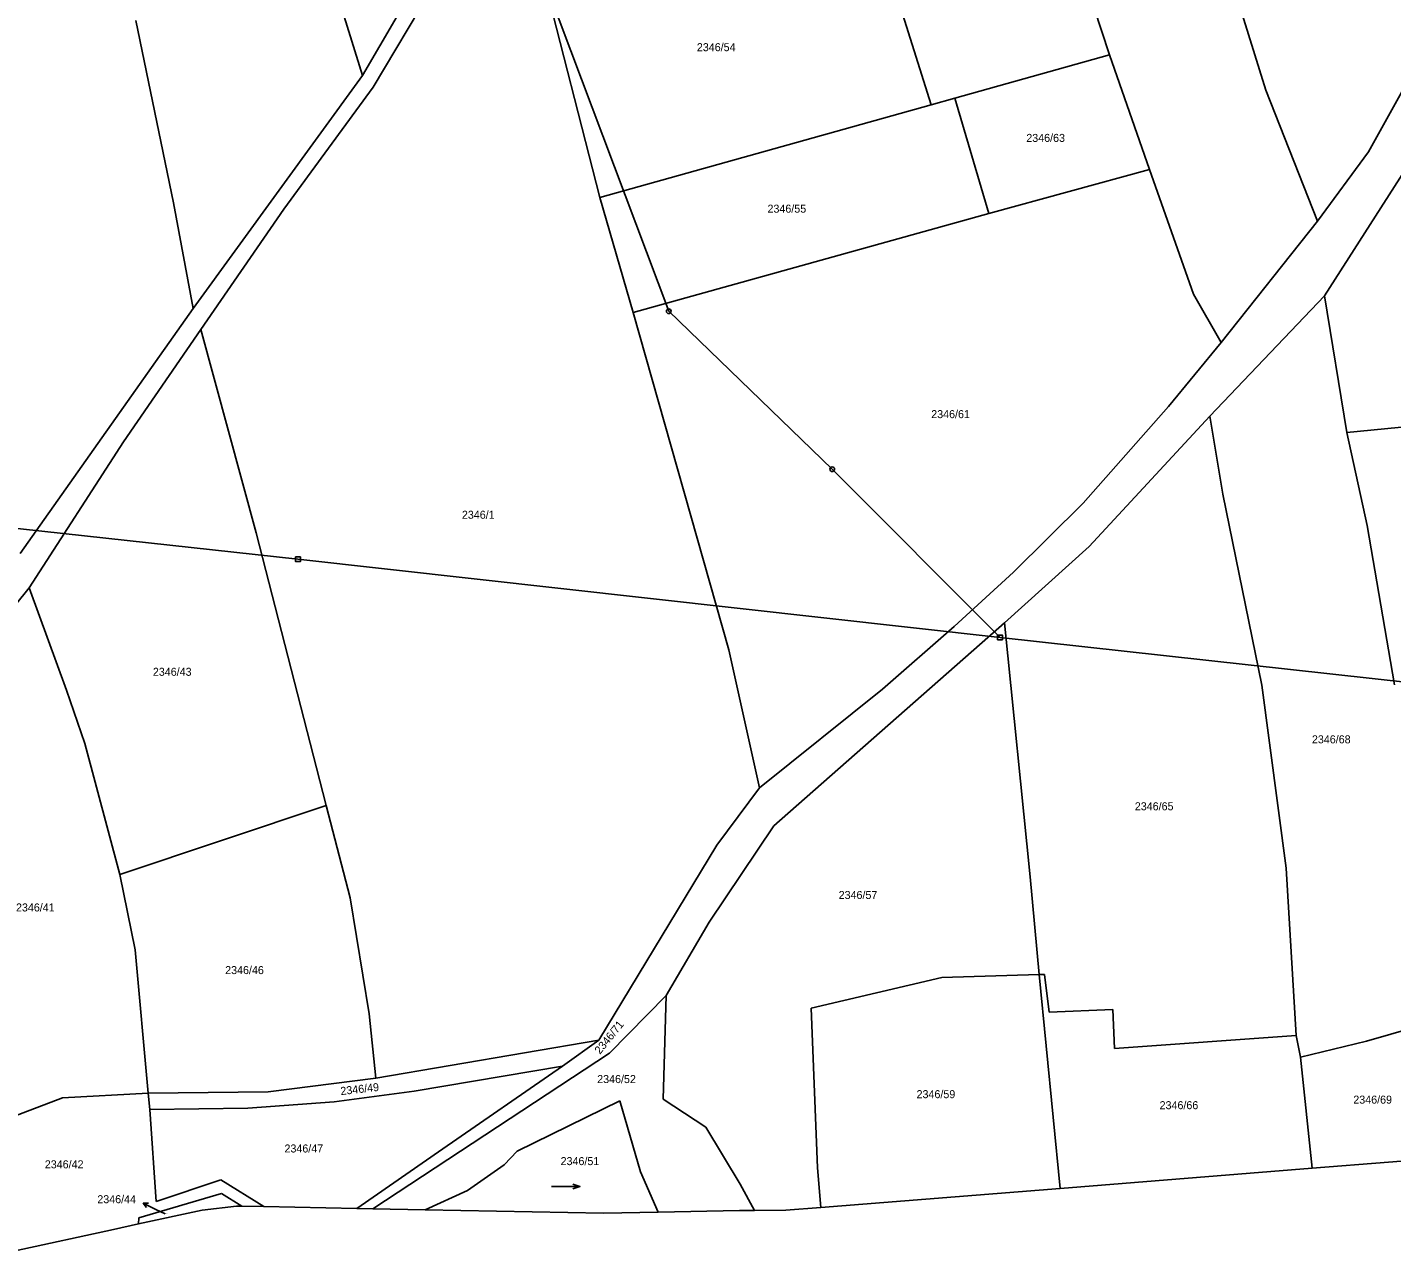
# Model space of a CAD drawing. Extents: x -785744 to -782822, y -1067550 to -1063910.
# Drawn here: x -783904.8 to -783615, y -1066980.3 to -1066720.6 of the extents above; entities that cross this region are included whole.
import ezdxf

# ---------------------------------------------------------------- set-up
doc = ezdxf.new("R2010")
doc.units = 0
for name, color, linetype in [('Hranice obce', 7, 'Continuous'), ('Hranice parcel', 7, 'Continuous'), ('Parcelní čísla', 7, 'Continuous'), ('Pop_ČP_popisy', 7, 'Continuous'), ('Poz_předměty', 7, 'Continuous'), ('Značky kultur', 7, 'Continuous')]:
    doc.layers.add(name, color=color, linetype=linetype)

msp = doc.modelspace()

# ---------------------------------------------------------------- linework, layer by layer
at = {"layer": 'Hranice obce'}
msp.add_lwpolyline([(-783599.47, -1066960.25), (-783631.87, -1066962.83), (-783685.39, -1066967.09), (-783736.23, -1066971.14), (-783743.66, -1066971.73), (-783750.35, -1066971.76), (-783753.49, -1066971.77), (-783770.8, -1066972.13), (-783782.39, -1066972.37), (-783820.29, -1066971.63), (-783831.37, -1066971.41), (-783834.77, -1066971.34), (-783854.54, -1066970.96), (-783859.2, -1066970.87), (-783860.35, -1066970.85), (-783867.66, -1066971.74), (-783881.13, -1066974.65), (-783886.43, -1066975.8), (-783907.33, -1066980.32)], dxfattribs=at)
at = {"layer": 'Hranice parcel'}
for points in [[(-783848.89, -1066681.55), (-783833.55, -1066730.81)], [(-783833.55, -1066730.81), (-783807.32, -1066685.82)], [(-783727.75, -1066689.56), (-783712.81, -1066737.08)], [(-783831.35, -1066733.28), (-783806.84, -1066692.19)], [(-783795.39, -1066708.79), (-783783.15, -1066756.76)], [(-783681.52, -1066706.35), (-783674.92, -1066726.45)], [(-783649.09, -1066710.21), (-783641.75, -1066733.95)], [(-783881.75, -1066719.16), (-783873.7, -1066757.85)], [(-783707.81, -1066735.67), (-783674.92, -1066726.45)], [(-783674.92, -1066726.45), (-783666.42, -1066750.77)], [(-783869.57, -1066780.28), (-783833.55, -1066730.81)], [(-783619.91, -1066747.05), (-783610.75, -1066730.49)], [(-783850.28, -1066759.19), (-783831.35, -1066733.28)], [(-783641.75, -1066733.95), (-783630.79, -1066761.74)], [(-783783.15, -1066756.76), (-783712.81, -1066737.08)], [(-783712.81, -1066737.08), (-783707.81, -1066735.67)], [(-783707.81, -1066735.67), (-783700.58, -1066760.13)], [(-783630.79, -1066761.74), (-783619.91, -1066747.05)], [(-783700.58, -1066760.13), (-783666.42, -1066750.77)], [(-783666.42, -1066750.77), (-783657.11, -1066777.22)], [(-783629.31, -1066777.59), (-783612.17, -1066750.86)], [(-783873.7, -1066757.85), (-783869.57, -1066780.28)], [(-783783.15, -1066756.76), (-783776.12, -1066781.13)], [(-783867.93, -1066784.77), (-783850.28, -1066759.19)], [(-783776.12, -1066781.13), (-783700.58, -1066760.13)], [(-783651.21, -1066787.53), (-783630.79, -1066761.74)], [(-783657.11, -1066777.22), (-783651.21, -1066787.53)], [(-783653.62, -1066803.18), (-783629.31, -1066777.59)], [(-783629.31, -1066777.59), (-783624.51, -1066806.6)], [(-783906.28, -1066832.31), (-783869.57, -1066780.28)], [(-783776.12, -1066781.13), (-783755.8, -1066852.77)], [(-783884.37, -1066808.58), (-783867.93, -1066784.77)], [(-783867.93, -1066784.77), (-783856.19, -1066827.92)], [(-783662.42, -1066801.1), (-783651.21, -1066787.53)], [(-783624.51, -1066806.6), (-783497.48, -1066794.21)], [(-783680.54, -1066821.63), (-783662.42, -1066801.1)], [(-783679.27, -1066830.79), (-783653.62, -1066803.18)], [(-783653.62, -1066803.18), (-783650.89, -1066819.72)], [(-783624.51, -1066806.6), (-783620.25, -1066826.33)], [(-783904.4, -1066839.63), (-783884.37, -1066808.58)], [(-783695.33, -1066836.25), (-783680.54, -1066821.63)], [(-783650.89, -1066819.72), (-783642.62, -1066860.28)], [(-783620.25, -1066826.33), (-783614.41, -1066860.16)], [(-783856.19, -1066827.92), (-783841.3, -1066885.79)], [(-783697.26, -1066847.06), (-783679.27, -1066830.79)], [(-783707.93, -1066847.77), (-783695.33, -1066836.25)], [(-783928.5, -1066869.5), (-783904.4, -1066839.63)], [(-783904.4, -1066839.63), (-783896.42, -1066861.31)], [(-783746.19, -1066890.14), (-783697.26, -1066847.06)], [(-783723.13, -1066861.11), (-783707.93, -1066847.77)], [(-783697.26, -1066847.06), (-783691.81, -1066900.92)], [(-783755.8, -1066852.77), (-783749.27, -1066882.04)], [(-783896.42, -1066861.31), (-783892.53, -1066872.62)], [(-783749.27, -1066882.04), (-783723.13, -1066861.11)], [(-783642.62, -1066860.28), (-783637.42, -1066899.1)], [(-783892.53, -1066872.62), (-783885.1, -1066900.45)], [(-783758.3, -1066894.23), (-783749.27, -1066882.04)], [(-783885.1, -1066900.45), (-783841.3, -1066885.79)], [(-783841.3, -1066885.79), (-783836.17, -1066905.4)], [(-783759.99, -1066910.56), (-783746.19, -1066890.14)], [(-783783.41, -1066935.64), (-783758.3, -1066894.23)], [(-783637.42, -1066899.1), (-783635.28, -1066934.61)], [(-783885.1, -1066900.45), (-783881.87, -1066916.43)], [(-783691.81, -1066900.92), (-783689.9, -1066921.71)], [(-783836.17, -1066905.4), (-783832.19, -1066930.03)], [(-783769.09, -1066926.14), (-783759.99, -1066910.56)], [(-783881.87, -1066916.43), (-783879.09, -1066946.85)], [(-783738.33, -1066928.85), (-783710.55, -1066922.34)], [(-783710.55, -1066922.34), (-783689.9, -1066921.71)], [(-783689.9, -1066921.71), (-783688.74, -1066921.65)], [(-783689.9, -1066921.71), (-783685.39, -1066967.09)], [(-783688.74, -1066921.65), (-783687.72, -1066929.7)], [(-783781.1, -1066938.35), (-783769.09, -1066926.14)], [(-783769.76, -1066948.12), (-783769.09, -1066926.14)], [(-783738.33, -1066928.85), (-783736.98, -1066962.72)], [(-783832.19, -1066930.03), (-783830.72, -1066943.66)], [(-783687.72, -1066929.7), (-783674.25, -1066929.14)], [(-783674.25, -1066929.14), (-783673.87, -1066937.42)], [(-783620.37, -1066935.83), (-783605.36, -1066931.49)], [(-783673.87, -1066937.42), (-783635.28, -1066934.61)], [(-783635.28, -1066934.61), (-783634.37, -1066939.24)], [(-783830.72, -1066943.66), (-783783.41, -1066935.64)], [(-783791.14, -1066941.14), (-783783.41, -1066935.64)], [(-783634.37, -1066939.24), (-783620.37, -1066935.83)], [(-783831.37, -1066971.41), (-783781.1, -1066938.35)], [(-783634.37, -1066939.24), (-783631.87, -1066962.83)], [(-783822.61, -1066946.47), (-783791.14, -1066941.14)], [(-783816.53, -1066958.72), (-783791.14, -1066941.14)], [(-783853.6, -1066946.58), (-783830.72, -1066943.66)], [(-783914.1, -1066954.26), (-783897.3, -1066947.84)], [(-783897.3, -1066947.84), (-783879.09, -1066946.85)], [(-783879.09, -1066946.85), (-783853.6, -1066946.58)], [(-783879.09, -1066946.85), (-783878.75, -1066950.32)], [(-783857.93, -1066950.06), (-783839.58, -1066948.69)], [(-783839.58, -1066948.69), (-783822.61, -1066946.47)], [(-783800.76, -1066959.16), (-783778.92, -1066948.47)], [(-783778.92, -1066948.47), (-783774.54, -1066963.56)], [(-783769.76, -1066948.12), (-783760.69, -1066954.09)], [(-783878.75, -1066950.32), (-783857.93, -1066950.06)], [(-783878.75, -1066950.32), (-783877.37, -1066969.84)], [(-783760.69, -1066954.09), (-783753.4, -1066966.17)], [(-783834.77, -1066971.34), (-783816.53, -1066958.72)], [(-783803.51, -1066962.07), (-783800.76, -1066959.16)], [(-783811.29, -1066967.57), (-783803.51, -1066962.07)], [(-783774.54, -1066963.56), (-783770.8, -1066972.13)], [(-783736.98, -1066962.72), (-783736.23, -1066971.14)], [(-783877.37, -1066969.84), (-783863.7, -1066965.28)], [(-783863.7, -1066965.28), (-783854.54, -1066970.96)], [(-783753.4, -1066966.17), (-783750.35, -1066971.76)], [(-783881.09, -1066973.33), (-783863.55, -1066968.19)], [(-783863.55, -1066968.19), (-783859.2, -1066970.87)], [(-783820.29, -1066971.63), (-783811.29, -1066967.57)], [(-783881.13, -1066974.65), (-783881.09, -1066973.33)]]:
    msp.add_lwpolyline(points, dxfattribs=at)
at = {"layer": 'Pop_ČP_popisy'}
msp.add_line((-783877.44, -1066971.57), (-783880.13, -1066970.24), dxfattribs=at)
for points in [[(-783879.45, -1066971.13), (-783880.13, -1066970.24), (-783879.01, -1066970.24)], [(-783875.52, -1066972.52), (-783877.44, -1066971.57)]]:
    msp.add_lwpolyline(points, dxfattribs=at)
at = {"layer": 'Poz_předměty'}
for points in [[(-783803.33, -1066688.31), (-783768.55, -1066780.87)], [(-783768.55, -1066780.87), (-783733.82, -1066814.41)], [(-783733.82, -1066814.41), (-783698.19, -1066850.13)], [(-783996.24, -1066817.26), (-783847.28, -1066833.54)], [(-783847.28, -1066833.54), (-783698.19, -1066850.13)], [(-783698.19, -1066850.13), (-783540.18, -1066867.55)]]:
    msp.add_lwpolyline(points, dxfattribs=at)
for points in [[(-783847.78, -1066833.04), (-783846.78, -1066833.04), (-783846.78, -1066834.04), (-783847.78, -1066834.04)], [(-783698.69, -1066849.63), (-783697.69, -1066849.63), (-783697.69, -1066850.63), (-783698.69, -1066850.63)]]:
    msp.add_lwpolyline(points, close=True, dxfattribs=at)
for centre in [(-783768.55, -1066780.87), (-783733.82, -1066814.41)]:
    msp.add_circle(centre, 0.5, dxfattribs=at)
at = {"layer": 'Značky kultur'}
for points in [[(-783793.42, -1066966.69), (-783787.42, -1066966.69), (-783788.92, -1066966.19)], [(-783787.42, -1066966.69), (-783788.92, -1066967.19)]]:
    msp.add_lwpolyline(points, dxfattribs=at)

# ---------------------------------------------------------------- texts
at = {"layer": 'Parcelní čísla'}
for s, height, p in [('2346/54', 1.7, (-783762.57, -1066725.67)), ('2346/63', 1.7, (-783692.61, -1066744.93)), ('2346/55', 1.7, (-783747.57, -1066759.95)), ('2346/61', 1.7, (-783712.8, -1066803.57)), ('2346/1', 1.7, (-783812.47, -1066824.93)), ('2346/43', 1.7, (-783878.1, -1066858.27)), ('2346/68', 1.7, (-783631.95, -1066872.61)), ('2346/65', 1.7, (-783669.56, -1066886.82)), ('2346/57', 1.7, (-783732.46, -1066905.65)), ('2346/41', 1.7, (-783907.17, -1066908.3)), ('2346/46', 1.7, (-783862.75, -1066921.6)), ('2346/52', 1.7, (-783783.74, -1066944.73)), ('2346/59', 1.7, (-783715.91, -1066947.94)), ('2346/66', 1.7, (-783664.3, -1066950.28)), ('2346/69', 1.7, (-783623.16, -1066949.1)), ('2346/47', 1.7, (-783850.15, -1066959.47)), ('2346/51', 1.7, (-783791.51, -1066962.15)), ('2346/42', 1.7, (-783901.05, -1066962.83)), ('2346/44', 0.1, (-783875.52, -1066972.52))]:
    msp.add_text(s, height=height, dxfattribs=at).set_placement(p)
msp.add_text('2346/49', height=1.7, rotation=6.3508, dxfattribs=at).set_placement((-783838.17, -1066947.29))
at = {"layer": 'Pop_ČP_popisy'}
msp.add_text('2346/71', height=1.7, rotation=50.9936, dxfattribs=at).set_placement((-783783.14, -1066938.73))
msp.add_text('2346/44', height=1.7, dxfattribs=at).set_placement((-783889.9, -1066970.24))

doc.saveas('drawing.dxf')
